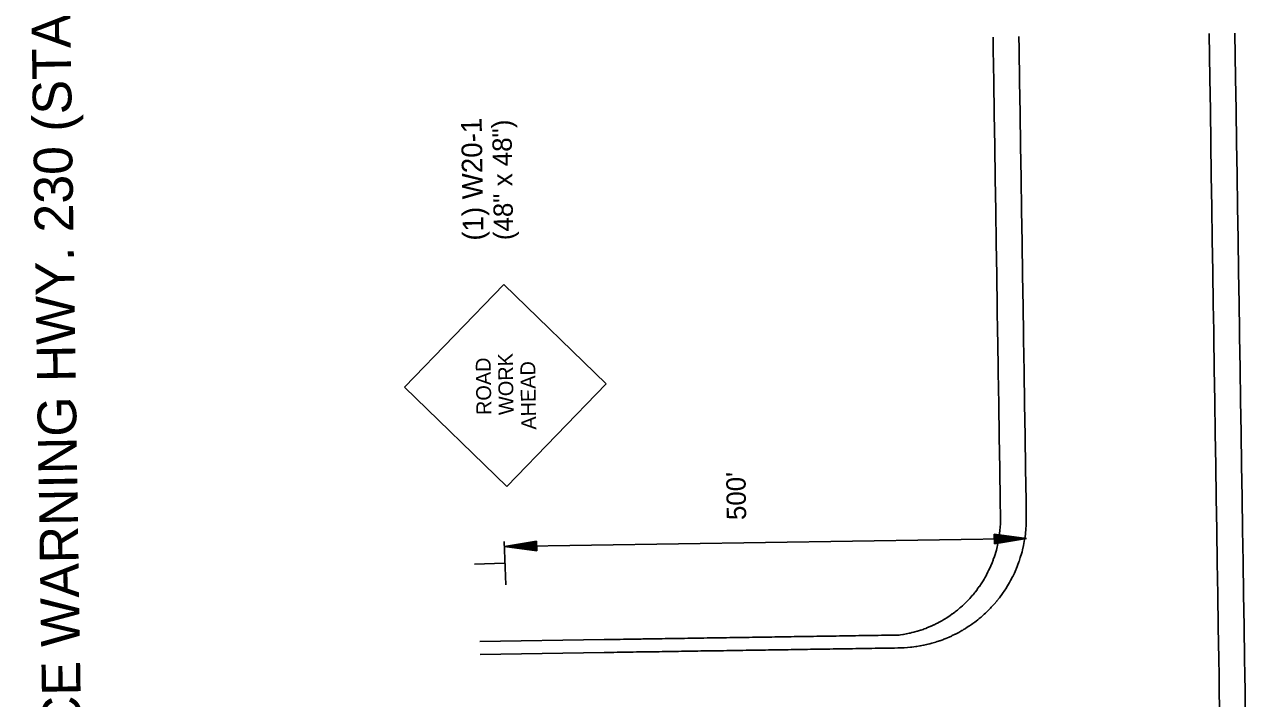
# Model space of a CAD drawing. Extents: x 1770018 to 1773492, y 718230 to 729141.
# Drawn here: x 1771495.6 to 1771874.2, y 720811.7 to 721020.6 of the extents above; entities that cross this region are included whole.
import ezdxf

# ---------------------------------------------------------------- set-up
doc = ezdxf.new("R2010")
doc.units = 0
for name, color, linetype in [('R_Dimension', 7, 'Continuous'), ('R_Draft', 7, 'Continuous'), ('R_MOT', 7, 'Continuous'), ('R_Proposed Road', 7, 'Continuous')]:
    doc.layers.add(name, color=color, linetype=linetype)

msp = doc.modelspace()

# ---------------------------------------------------------------- linework, layer by layer
at = {"layer": 'R_Dimension'}
for p, q in [((1771644.44, 720858.82), (1771806.34, 720861.31)), ((1771796.32, 720862.66), (1771806.34, 720861.31)), ((1771796.37, 720859.66), (1771796.32, 720862.66)), ((1771796.32, 720862.41), (1771804.67, 720861.29)), ((1771796.33, 720862.15), (1771802.95, 720861.26)), ((1771796.33, 720861.9), (1771801.29, 720861.23)), ((1771796.34, 720861.65), (1771799.59, 720861.21)), ((1771796.34, 720861.39), (1771797.92, 720861.18)), ((1771796.35, 720860.41), (1771801.29, 720861.23)), ((1771796.35, 720860.67), (1771799.59, 720861.21)), ((1771796.35, 720860.92), (1771797.92, 720861.18)), ((1771796.36, 720859.91), (1771804.67, 720861.29)), ((1771796.36, 720860.16), (1771802.95, 720861.26)), ((1771796.37, 720859.66), (1771806.34, 720861.31)), ((1771654.42, 720860.47), (1771644.44, 720858.82)), ((1771654.47, 720857.47), (1771644.44, 720858.82)), ((1771654.42, 720860.22), (1771646.11, 720858.84)), ((1771654.46, 720857.72), (1771646.11, 720858.84)), ((1771654.43, 720859.97), (1771647.83, 720858.87)), ((1771654.46, 720857.98), (1771647.83, 720858.87)), ((1771654.43, 720859.72), (1771649.5, 720858.9)), ((1771654.45, 720858.23), (1771649.5, 720858.9)), ((1771654.44, 720859.46), (1771651.19, 720858.92)), ((1771654.45, 720858.49), (1771651.19, 720858.92)), ((1771654.44, 720859.21), (1771652.86, 720858.95)), ((1771654.45, 720858.74), (1771652.86, 720858.95)), ((1771654.47, 720857.47), (1771654.42, 720860.47))]:
    msp.add_line(p, q, dxfattribs=at)
at = {"layer": 'R_MOT'}
for p, q in [((1771644.22, 720939.98), (1771613.44, 720908.23)), ((1771644.22, 720939.98), (1771675.95, 720909.19)), ((1771613.44, 720908.23), (1771645.19, 720877.44)), ((1771675.95, 720909.19), (1771645.19, 720877.44)), ((1771644.39, 720860.4), (1771644.82, 720846.9)), ((1771644.41, 720853.68), (1771635.2, 720853.38))]:
    msp.add_line(p, q, dxfattribs=at)
at = {"layer": 'R_Proposed Road'}
for p, q in [((1771675.32, 720829.98), (1771636.83, 720829.39)), ((1771675.38, 720825.98), (1771636.89, 720825.39))]:
    msp.add_line(p, q, dxfattribs=at)
for points in [[(1771795.95, 721016.69), (1771796.01, 721012.86), (1771796.16, 721002.86), (1771796.31, 720992.87), (1771796.47, 720982.87), (1771796.62, 720972.87), (1771796.78, 720962.87), (1771796.93, 720952.87), (1771797.08, 720942.87), (1771797.24, 720932.87), (1771797.36, 720924.66), (1771797.36, 720924.65), (1771797.39, 720922.87), (1771797.55, 720912.88), (1771797.7, 720902.88), (1771797.85, 720892.88), (1771798.01, 720882.88), (1771798.16, 720872.88), (1771798.24, 720867.88)], [(1771803.95, 721016.82), (1771804, 721012.99), (1771804.16, 721002.99), (1771804.31, 720992.99), (1771804.47, 720982.99), (1771804.62, 720972.99), (1771804.77, 720962.99), (1771804.93, 720952.99), (1771805.08, 720943), (1771805.24, 720933), (1771805.36, 720924.78), (1771805.36, 720924.78), (1771805.39, 720923), (1771805.55, 720913), (1771805.7, 720903), (1771805.85, 720893), (1771806.01, 720883), (1771806.16, 720873), (1771806.24, 720868)], [(1771862.94, 721017.73), (1771863.15, 721003.9), (1771863.31, 720993.9), (1771863.46, 720983.9), (1771863.61, 720973.9), (1771863.77, 720963.9), (1771863.92, 720953.9), (1771864.08, 720943.9), (1771864.23, 720933.91), (1771864.36, 720925.69), (1771864.36, 720925.69), (1771864.38, 720923.91), (1771864.54, 720913.91), (1771864.69, 720903.91), (1771864.85, 720893.91), (1771865, 720883.91), (1771865.15, 720873.91), (1771865.31, 720863.91), (1771865.46, 720853.91), (1771865.62, 720843.92), (1771865.77, 720833.92), (1771865.92, 720823.92), (1771866, 720818.92), (1771866.08, 720813.92), (1771866.23, 720803.92)], [(1771870.94, 721017.85), (1771871.15, 721004.02), (1771871.3, 720994.02), (1771871.46, 720984.02), (1771871.61, 720974.02), (1771871.77, 720964.03), (1771871.92, 720954.03), (1771872.07, 720944.03), (1771872.23, 720934.03), (1771872.36, 720925.81), (1771872.36, 720925.81), (1771872.38, 720924.03), (1771872.54, 720914.03), (1771872.69, 720904.03), (1771872.85, 720894.03), (1771873, 720884.03), (1771873.15, 720874.04), (1771873.31, 720864.04), (1771873.46, 720854.04), (1771873.62, 720844.04), (1771873.77, 720834.04), (1771873.92, 720824.04), (1771874, 720819.04), (1771874.08, 720814.04), (1771874.23, 720804.04)], [(1771798.24, 720867.88), (1771798.24, 720866.86), (1771798.21, 720865.83), (1771798.16, 720864.8), (1771798.07, 720863.78), (1771797.97, 720862.82), (1771797.96, 720862.76), (1771797.82, 720861.74), (1771797.64, 720860.73), (1771797.44, 720859.72), (1771797.32, 720859.14), (1771797.22, 720858.71), (1771796.96, 720857.71), (1771796.67, 720856.72), (1771796.65, 720856.63), (1771796.36, 720855.73), (1771796.02, 720854.75), (1771795.96, 720854.61), (1771795.64, 720853.78), (1771795.27, 720852.88), (1771795.24, 720852.82), (1771794.82, 720851.87), (1771794.57, 720851.35), (1771794.36, 720850.93), (1771793.88, 720850), (1771793.86, 720849.97), (1771793.36, 720849.08), (1771793.14, 720848.71), (1771792.82, 720848.18), (1771792.42, 720847.54), (1771792.26, 720847.29), (1771791.69, 720846.46), (1771791.66, 720846.42), (1771791.04, 720845.56), (1771790.96, 720845.45), (1771790.39, 720844.71), (1771790.22, 720844.49), (1771790.06, 720844.3), (1771789.72, 720843.89), (1771789.47, 720843.6), (1771789.02, 720843.08), (1771788.72, 720842.75), (1771788.29, 720842.29), (1771787.96, 720841.95), (1771787.53, 720841.52), (1771787.2, 720841.19), (1771786.76, 720840.77), (1771786.43, 720840.47), (1771785.95, 720840.04), (1771785.66, 720839.78), (1771785.13, 720839.33), (1771784.87, 720839.13), (1771784.28, 720838.65), (1771784.09, 720838.51), (1771783.69, 720838.21), (1771783.4, 720837.99), (1771783.3, 720837.92), (1771782.5, 720837.36), (1771782.5, 720837.36), (1771781.7, 720836.82), (1771781.58, 720836.75), (1771780.89, 720836.32), (1771780.64, 720836.17), (1771780.08, 720835.84), (1771779.68, 720835.61), (1771779.26, 720835.38), (1771778.7, 720835.09), (1771778.44, 720834.96), (1771777.7, 720834.59), (1771777.61, 720834.55), (1771776.78, 720834.17), (1771776.68, 720834.12), (1771775.94, 720833.81), (1771775.64, 720833.69), (1771775.09, 720833.47), (1771774.58, 720833.28), (1771774.24, 720833.16), (1771773.51, 720832.91), (1771773.39, 720832.87), (1771772.52, 720832.6), (1771772.42, 720832.57), (1771771.66, 720832.35), (1771771.32, 720832.26), (1771770.79, 720832.13), (1771770.21, 720831.99), (1771769.91, 720831.93), (1771769.08, 720831.76), (1771769.03, 720831.75), (1771768.14, 720831.59), (1771767.94, 720831.56), (1771767.25, 720831.45), (1771766.8, 720831.39), (1771766.3, 720831.38), (1771765.3, 720831.37), (1771764.3, 720831.35), (1771763.3, 720831.34), (1771762.3, 720831.32), (1771761.3, 720831.31), (1771760.3, 720831.29), (1771759.3, 720831.28), (1771758.3, 720831.26), (1771757.3, 720831.25), (1771756.3, 720831.23), (1771755.3, 720831.22), (1771754.3, 720831.2), (1771753.3, 720831.18), (1771752.3, 720831.17), (1771751.3, 720831.15), (1771750.3, 720831.14), (1771749.3, 720831.12), (1771748.3, 720831.11), (1771747.3, 720831.09), (1771746.3, 720831.08), (1771745.3, 720831.06), (1771744.3, 720831.05), (1771743.3, 720831.03), (1771742.3, 720831.01), (1771741.3, 720831), (1771740.3, 720830.98), (1771739.3, 720830.97), (1771738.3, 720830.95), (1771737.3, 720830.94), (1771736.3, 720830.92), (1771735.3, 720830.91), (1771734.3, 720830.89), (1771733.3, 720830.88), (1771732.3, 720830.86), (1771731.3, 720830.85), (1771730.3, 720830.83), (1771729.3, 720830.81), (1771728.3, 720830.8), (1771727.3, 720830.78), (1771726.3, 720830.77), (1771725.3, 720830.75), (1771724.3, 720830.74), (1771723.3, 720830.72), (1771722.3, 720830.71), (1771721.3, 720830.69), (1771720.3, 720830.68), (1771719.3, 720830.66), (1771718.3, 720830.65), (1771717.3, 720830.63), (1771716.3, 720830.61), (1771715.3, 720830.6), (1771714.3, 720830.58), (1771713.3, 720830.57), (1771712.3, 720830.55), (1771711.3, 720830.54), (1771710.3, 720830.52), (1771709.3, 720830.51), (1771708.3, 720830.49), (1771707.3, 720830.48), (1771706.3, 720830.46), (1771705.3, 720830.44), (1771704.31, 720830.43), (1771703.31, 720830.41), (1771702.31, 720830.4), (1771701.31, 720830.38), (1771700.31, 720830.37), (1771699.31, 720830.35), (1771698.31, 720830.34), (1771697.31, 720830.32), (1771696.31, 720830.31), (1771695.31, 720830.29), (1771694.31, 720830.28), (1771693.31, 720830.26), (1771692.31, 720830.24), (1771691.31, 720830.23), (1771690.31, 720830.21), (1771689.31, 720830.2), (1771688.31, 720830.18), (1771687.31, 720830.17), (1771686.81, 720830.16), (1771686.31, 720830.15), (1771685.31, 720830.14), (1771684.31, 720830.12), (1771683.31, 720830.11), (1771682.31, 720830.09), (1771681.31, 720830.08), (1771680.31, 720830.06), (1771679.31, 720830.04), (1771678.31, 720830.03), (1771677.58, 720830.02), (1771677.31, 720830.01), (1771676.32, 720830), (1771675.32, 720829.98), (1771675.32, 720829.98)], [(1771806.24, 720868), (1771806.24, 720866.72), (1771806.2, 720865.44), (1771806.11, 720864.16), (1771805.99, 720862.88), (1771805.84, 720861.69), (1771805.82, 720861.61), (1771805.62, 720860.35), (1771805.37, 720859.09), (1771805.09, 720857.84), (1771804.91, 720857.13), (1771804.76, 720856.6), (1771804.39, 720855.37), (1771803.99, 720854.15), (1771803.95, 720854.05), (1771803.55, 720852.95), (1771803.06, 720851.76), (1771802.99, 720851.59), (1771802.54, 720850.59), (1771802.02, 720849.5), (1771801.99, 720849.43), (1771801.39, 720848.3), (1771801.05, 720847.68), (1771800.76, 720847.18), (1771800.1, 720846.09), (1771800.08, 720846.05), (1771799.4, 720845.01), (1771799.1, 720844.57), (1771798.66, 720843.96), (1771798.12, 720843.22), (1771797.9, 720842.93), (1771797.14, 720841.98), (1771797.1, 720841.93), (1771796.26, 720840.96), (1771796.16, 720840.83), (1771795.4, 720840.01), (1771795.17, 720839.76), (1771794.96, 720839.54), (1771794.51, 720839.09), (1771794.19, 720838.77), (1771793.59, 720838.19), (1771793.2, 720837.84), (1771792.64, 720837.33), (1771792.21, 720836.97), (1771791.66, 720836.5), (1771791.23, 720836.15), (1771790.66, 720835.7), (1771790.24, 720835.38), (1771789.63, 720834.94), (1771789.25, 720834.67), (1771788.58, 720834.2), (1771788.26, 720833.99), (1771787.5, 720833.51), (1771787.27, 720833.36), (1771786.77, 720833.06), (1771786.41, 720832.84), (1771786.28, 720832.77), (1771785.29, 720832.21), (1771785.29, 720832.21), (1771784.3, 720831.69), (1771784.15, 720831.62), (1771783.3, 720831.21), (1771783, 720831.07), (1771782.31, 720830.76), (1771781.82, 720830.55), (1771781.32, 720830.34), (1771780.63, 720830.07), (1771780.32, 720829.95), (1771779.43, 720829.62), (1771779.33, 720829.59), (1771778.33, 720829.26), (1771778.21, 720829.22), (1771777.34, 720828.96), (1771776.98, 720828.86), (1771776.34, 720828.68), (1771775.74, 720828.53), (1771775.34, 720828.44), (1771774.49, 720828.25), (1771774.35, 720828.22), (1771773.35, 720828.02), (1771773.23, 720828), (1771772.35, 720827.86), (1771771.97, 720827.8), (1771771.35, 720827.72), (1771770.7, 720827.64), (1771770.36, 720827.6), (1771769.42, 720827.51), (1771769.36, 720827.51), (1771768.36, 720827.44), (1771768.14, 720827.43), (1771767.36, 720827.4), (1771766.86, 720827.39), (1771766.36, 720827.38), (1771765.36, 720827.37), (1771764.36, 720827.35), (1771763.36, 720827.34), (1771762.36, 720827.32), (1771761.36, 720827.31), (1771760.36, 720827.29), (1771759.36, 720827.28), (1771758.36, 720827.26), (1771757.36, 720827.25), (1771756.36, 720827.23), (1771755.36, 720827.22), (1771754.36, 720827.2), (1771753.36, 720827.18), (1771752.36, 720827.17), (1771751.36, 720827.15), (1771750.36, 720827.14), (1771749.36, 720827.12), (1771748.36, 720827.11), (1771747.36, 720827.09), (1771746.36, 720827.08), (1771745.36, 720827.06), (1771744.36, 720827.05), (1771743.36, 720827.03), (1771742.36, 720827.02), (1771741.36, 720827), (1771740.36, 720826.98), (1771739.36, 720826.97), (1771738.36, 720826.95), (1771737.36, 720826.94), (1771736.36, 720826.92), (1771735.36, 720826.91), (1771734.36, 720826.89), (1771733.36, 720826.88), (1771732.36, 720826.86), (1771731.36, 720826.85), (1771730.36, 720826.83), (1771729.36, 720826.81), (1771728.36, 720826.8), (1771727.36, 720826.78), (1771726.36, 720826.77), (1771725.36, 720826.75), (1771724.36, 720826.74), (1771723.36, 720826.72), (1771722.36, 720826.71), (1771721.36, 720826.69), (1771720.36, 720826.68), (1771719.36, 720826.66), (1771718.36, 720826.65), (1771717.37, 720826.63), (1771716.37, 720826.61), (1771715.37, 720826.6), (1771714.37, 720826.58), (1771713.37, 720826.57), (1771712.37, 720826.55), (1771711.37, 720826.54), (1771710.37, 720826.52), (1771709.37, 720826.51), (1771708.37, 720826.49), (1771707.37, 720826.48), (1771706.37, 720826.46), (1771705.37, 720826.45), (1771704.37, 720826.43), (1771703.37, 720826.41), (1771702.37, 720826.4), (1771701.37, 720826.38), (1771700.37, 720826.37), (1771699.37, 720826.35), (1771698.37, 720826.34), (1771697.37, 720826.32), (1771696.37, 720826.31), (1771695.37, 720826.29), (1771694.37, 720826.28), (1771693.37, 720826.26), (1771692.37, 720826.24), (1771691.37, 720826.23), (1771690.37, 720826.21), (1771689.37, 720826.2), (1771688.37, 720826.18), (1771687.37, 720826.17), (1771686.87, 720826.16), (1771686.37, 720826.15), (1771685.37, 720826.14), (1771684.37, 720826.12), (1771683.37, 720826.11), (1771682.37, 720826.09), (1771681.37, 720826.08), (1771680.37, 720826.06), (1771679.37, 720826.04), (1771678.37, 720826.03), (1771677.64, 720826.02), (1771677.37, 720826.01), (1771676.38, 720826), (1771675.38, 720825.98)]]:
    msp.add_lwpolyline(points, dxfattribs=at)

# ---------------------------------------------------------------- texts
at = {"layer": 'R_Dimension'}
msp.add_text("500'", height=6, rotation=90.8827, dxfattribs=at).set_placement((1771719.4, 720867.06))
at = {"layer": 'R_Draft'}
msp.add_text('ADVANCE WARNING HWY. 230 (STAGES 1, 2, & 3)', height=12, rotation=90.8827, dxfattribs=at).set_placement((1771514.06, 720745.83))
at = {"layer": 'R_MOT'}
for s, height, rotation, p in [('(1) W20-1', 6.4, 90.8827, (1771637.96, 720953.65)), ('(48" x 48")', 5.9994, 90.8827, (1771647.17, 720953.79)), ('WORK', 4.607, 90.8827, (1771647.3, 720899.62)), ('ROAD', 4.607, 90.8831, (1771640.39, 720899.61)), (' AHEAD ', 4.607, 90.8833, (1771654.31, 720893.35))]:
    msp.add_text(s, height=height, rotation=rotation, dxfattribs=at).set_placement(p)

doc.saveas('drawing.dxf')
